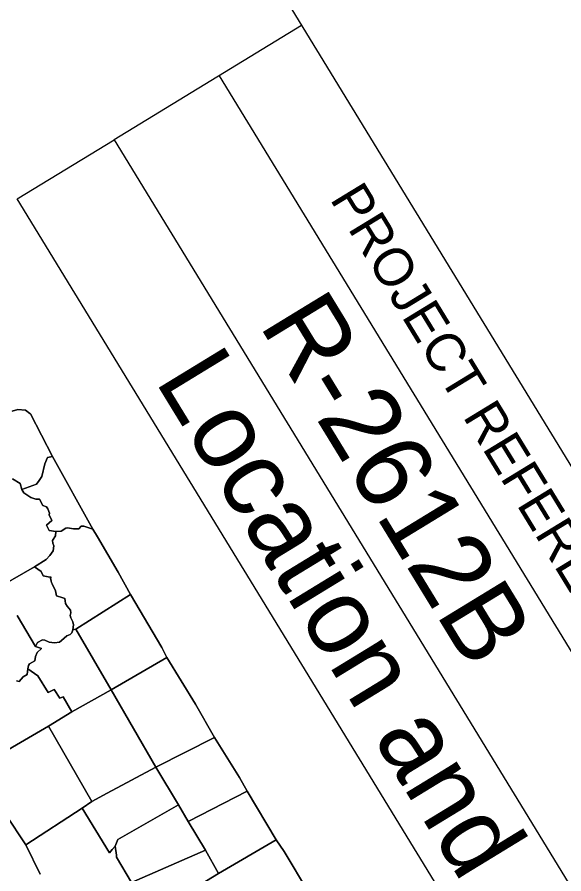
# Model space of a CAD drawing. Extents: x 1771071 to 1790027, y 804210 to 823391.
# Drawn here: x 1788245 to 1788984, y 810546 to 811705 of the extents above; entities that cross this region are included whole.
import ezdxf

# ---------------------------------------------------------------- set-up
doc = ezdxf.new("R2010")
doc.units = 0
for name, color, linetype in [('Prop Conc 2ft 6in Curb and Gutter', 7, 'Continuous'), ('Prop Horizontal Alignment', 7, 'Continuous'), ('Scratch_Level_4', 7, 'Continuous')]:
    doc.layers.add(name, color=color, linetype=linetype)

msp = doc.modelspace()

# ---------------------------------------------------------------- linework, layer by layer
at = {"layer": 'Prop Conc 2ft 6in Curb and Gutter'}
msp.add_lwpolyline([(1789711.9, 809923), (1781551.1, 823279.4), (1772201.7, 817566.9), (1780362.5, 804210.5)], close=True, dxfattribs=at)
at = {"layer": 'Prop Horizontal Alignment'}
for p, q in [((1788629.2, 811694), (1788375.8, 811539.1)), ((1788517.9, 811625.9), (1789600.1, 809854.7))]:
    msp.add_line(p, q, dxfattribs=at)
msp.add_lwpolyline([(1788375.8, 811539.1), (1789458, 809767.9), (1789327, 809687.8), (1788244.7, 811459.1)], close=True, dxfattribs=at)
at = {"layer": 'Scratch_Level_4'}
msp.add_line((1788345.5, 810643.4), (1788366.5, 810654.9), dxfattribs=at)
for points in [[(1788237.8, 811171.8), (1788245.7, 811174.1), (1788255.7, 811173.3), (1788261.7, 811168.6), (1788262.8, 811168.3), (1788292.2, 811110.3)], [(1788638.7, 810520.7), (1788605.9, 810575.8), (1788595.1, 810591.6), (1788555.6, 810657.5), (1788545.4, 810676), (1788511.8, 810730), (1788485.7, 810775.4), (1788447.3, 810838.5), (1788440.4, 810851.9), (1788398.1, 810923.7), (1788381.1, 810953.8), (1788353.3, 811001.7), (1788346.8, 811012), (1788292.2, 811110.3), (1788262.8, 811168.3), (1788261.7, 811168.6), (1788255.7, 811173.3), (1788245.7, 811174.1), (1788237.8, 811171.8)], [(1788292.2, 811110.3), (1788285.5, 811109.3), (1788282.1, 811100.6), (1788278, 811083.4), (1788274.2, 811078.2), (1788270.6, 811073.1), (1788251.1, 811065.7), (1788248.6, 811074), (1788238.1, 811080.4)], [(1788346.8, 811012), (1788334.7, 811016.3), (1788331.3, 811016), (1788328, 811012.8), (1788320.9, 811012.8), (1788312.9, 811014.1), (1788310.4, 811013.4), (1788304.2, 811009.4), (1788297, 811008.9), (1788288, 811010.2), (1788284.4, 811017.7), (1788291.4, 811023.9), (1788287.9, 811031.4), (1788288.3, 811033.7), (1788286.2, 811039.7), (1788284.3, 811042.5), (1788279.3, 811044.3), (1788275, 811052.7), (1788270, 811052.7), (1788263, 811055.2), (1788253.6, 811061.3), (1788251.1, 811065.7), (1788270.6, 811073.1), (1788274.2, 811078.2), (1788278, 811083.4), (1788282.1, 811100.6), (1788285.5, 811109.3), (1788292.2, 811110.3), (1788346.8, 811012)], [(1788238.1, 811080.4), (1788248.6, 811074), (1788251.1, 811065.7), (1788253.6, 811061.3), (1788263, 811055.2), (1788270, 811052.7), (1788275, 811052.7), (1788279.3, 811044.3), (1788284.3, 811042.5), (1788286.2, 811039.7), (1788288.3, 811033.7), (1788287.9, 811031.4), (1788291.4, 811023.9), (1788284.4, 811017.7), (1788288, 811010.2), (1788297, 811008.9)], [(1788297, 811008.9), (1788296.6, 811003), (1788292.5, 810997), (1788293, 810993.2), (1788294.2, 810989.5), (1788293.4, 810983), (1788288.7, 810976.4), (1788283.8, 810971.2), (1788268.2, 810961.1), (1788223.2, 810935.3)], [(1788324, 810877), (1788319.9, 810876), (1788321, 810882.6), (1788320, 810886.8), (1788317.1, 810892), (1788316.1, 810895.2), (1788317.4, 810899), (1788316.8, 810902.3), (1788312.3, 810908), (1788310.1, 810911.4), (1788309.7, 810915.1), (1788309, 810918.4), (1788306.2, 810919.1), (1788297.9, 810922.1), (1788296.6, 810928.7), (1788292, 810938), (1788291.1, 810940.1), (1788290.5, 810941.6), (1788289.9, 810945.7), (1788290.4, 810947), (1788286.6, 810947.6), (1788279.9, 810949.1), (1788276.9, 810954.7), (1788268.2, 810961.1), (1788283.8, 810971.2), (1788288.7, 810976.4), (1788293.4, 810983), (1788294.2, 810989.5), (1788293, 810993.2), (1788292.5, 810997), (1788296.6, 811003), (1788297, 811008.9), (1788304.2, 811009.4), (1788310.4, 811013.4), (1788312.9, 811014.1), (1788320.9, 811012.8), (1788328, 811012.8), (1788331.3, 811016), (1788334.7, 811016.3), (1788346.8, 811012), (1788353.3, 811001.7), (1788381.1, 810953.8), (1788398.1, 810923.7), (1788324, 810877)], [(1788223.2, 810935.3), (1788268.2, 810961.1), (1788276.9, 810954.7), (1788279.9, 810949.1), (1788286.6, 810947.6), (1788290.4, 810947), (1788289.9, 810945.7), (1788290.5, 810941.6), (1788291.1, 810940.1), (1788292, 810938), (1788296.6, 810928.7), (1788297.9, 810922.1), (1788306.2, 810919.1), (1788309, 810918.4), (1788309.7, 810915.1), (1788310.1, 810911.4), (1788312.3, 810908), (1788316.8, 810902.3)], [(1788447.3, 810838.5), (1788371.9, 810794.9), (1788324, 810877), (1788398.1, 810923.7), (1788440.4, 810851.9), (1788447.3, 810838.5)], [(1788316.8, 810902.3), (1788317.4, 810899), (1788316.1, 810895.2), (1788317.1, 810892), (1788320, 810886.8), (1788321, 810882.6), (1788319.9, 810876), (1788318.7, 810871.9), (1788316.2, 810869.5), (1788311.7, 810867.6), (1788304.7, 810861.6), (1788301.8, 810859), (1788295.2, 810858.1), (1788288.1, 810859.1), (1788282.2, 810862.1), (1788279, 810862.2), (1788272.3, 810858.7), (1788269.3, 810853.2), (1788244.4, 810895.5)], [(1788244.4, 810895.5), (1788269.3, 810853.2), (1788273.4, 810852), (1788277.4, 810850.8)], [(1788324, 810877), (1788371.9, 810794.9), (1788318.7, 810764.9), (1788306.8, 810785.3), (1788302.3, 810783.5), (1788294.7, 810795.1), (1788286.5, 810791), (1788272.7, 810813.6), (1788259, 810822.9), (1788259.9, 810827.6), (1788261.3, 810830), (1788268.5, 810834), (1788269.2, 810839.9), (1788271.6, 810845.2), (1788277.4, 810850.8), (1788273.4, 810852), (1788269.3, 810853.2), (1788272.3, 810858.7), (1788279, 810862.2), (1788282.2, 810862.1), (1788288.1, 810859.1), (1788295.2, 810858.1), (1788301.8, 810859), (1788304.7, 810861.6), (1788311.7, 810867.6), (1788316.2, 810869.5), (1788318.7, 810871.9), (1788319.9, 810876), (1788324, 810877)], [(1788277.4, 810850.8), (1788271.6, 810845.2), (1788269.2, 810839.9), (1788268.5, 810834), (1788261.3, 810830), (1788259.9, 810827.6), (1788259, 810822.9), (1788258.2, 810815.5), (1788252.8, 810812.2), (1788247.3, 810806.1), (1788243.5, 810806.7)], [(1788485.7, 810775.4), (1788511.8, 810730), (1788432.4, 810689.9), (1788371.9, 810794.9), (1788447.3, 810838.5), (1788485.7, 810775.4)], [(1788243.5, 810806.7), (1788247.3, 810806.1), (1788252.8, 810812.2), (1788258.2, 810815.5), (1788259, 810822.9), (1788272.7, 810813.6), (1788286.5, 810791), (1788294.7, 810795.1), (1788302.3, 810783.5), (1788306.8, 810785.3)], [(1788432.4, 810689.9), (1788366.5, 810654.9), (1788345.5, 810643.4), (1788287.2, 810745.7), (1788318.7, 810764.9), (1788371.9, 810794.9), (1788432.4, 810689.9)], [(1788371.9, 810794.9), (1788318.7, 810764.9), (1788287.2, 810745.7), (1788345.5, 810643.4)], [(1788366.5, 810654.9), (1788432.4, 810689.9), (1788371.9, 810794.9)], [(1788306.8, 810785.3), (1788318.7, 810764.9), (1788287.2, 810745.7), (1788187.1, 810687.3)], [(1788332.7, 810634.4), (1788256.5, 810585), (1788228.6, 810626.5), (1788187.1, 810687.3), (1788287.2, 810745.7), (1788345.5, 810643.4), (1788332.7, 810634.4)], [(1788555.6, 810657.5), (1788475.9, 810616.3), (1788463, 810639), (1788432.4, 810689.9), (1788511.8, 810730), (1788545.4, 810676), (1788555.6, 810657.5)], [(1788377.3, 810583.3), (1788373, 810578.4), (1788369.4, 810574.1), (1788332.7, 810634.4), (1788345.5, 810643.4), (1788366.5, 810654.9), (1788432.4, 810689.9), (1788463, 810639), (1788380.8, 810592.1), (1788377.3, 810583.3)], [(1788555.6, 810657.5), (1788595.1, 810591.6), (1788516.8, 810545.9), (1788499.4, 810577.5), (1788475.9, 810616.3), (1788555.6, 810657.5)], [(1788475.9, 810616.3), (1788499.4, 810577.5), (1788399.1, 810533.8), (1788379.2, 810568.1), (1788379.1, 810570.9), (1788377.3, 810583.3), (1788380.8, 810592.1), (1788463, 810639), (1788475.9, 810616.3)], [(1788155.7, 810543.9), (1788158.5, 810551), (1788159.1, 810557.9), (1788164.9, 810560.9), (1788170.3, 810567.3), (1788171.6, 810571), (1788169.4, 810574.7), (1788169, 810577.3), (1788171.7, 810580.2), (1788185.8, 810588.3), (1788210.7, 810611.2), (1788228.6, 810626.5), (1788256.5, 810585), (1788275.5, 810545.3)], [(1788275.5, 810545.3), (1788256.5, 810585), (1788332.7, 810634.4), (1788369.4, 810574.1), (1788373, 810578.4), (1788377.3, 810583.3), (1788379.1, 810570.9), (1788379.2, 810568.1), (1788399.1, 810533.8)], [(1788638.7, 810520.7), (1788618.9, 810522.7), (1788614.6, 810522.1), (1788540.5, 810477.4), (1788531.2, 810471.6), (1788525.7, 810470.6), (1788507.7, 810467.2), (1788505.1, 810462.3), (1788495.9, 810459.1), (1788490.8, 810497.2), (1788481.7, 810511.4), (1788478, 810509.2), (1788478, 810516.3), (1788480.1, 810522.5), (1788486.9, 810527.6), (1788516.8, 810545.9), (1788595.1, 810591.6), (1788605.9, 810575.8), (1788638.7, 810520.7)], [(1788499.4, 810577.5), (1788516.8, 810545.9), (1788486.9, 810527.6), (1788480.1, 810522.5), (1788478, 810516.3), (1788478, 810509.2), (1788473.3, 810506), (1788473.6, 810502.6), (1788476.9, 810499.6), (1788476.6, 810495.9), (1788471.1, 810492), (1788464.6, 810489.2), (1788453.5, 810488.8), (1788444.4, 810491.6), (1788440.7, 810500.1), (1788420.1, 810497.4), (1788412.5, 810508.6), (1788399.1, 810533.8), (1788499.4, 810577.5)]]:
    msp.add_lwpolyline(points, dxfattribs=at)

# ---------------------------------------------------------------- texts
at = {"layer": 'Prop Horizontal Alignment'}
for s, height, p in [('PROJECT REFERENCE NO.', 52.175, (1788666.9, 811459.1)), ('R-2612B', 104.35, (1788571.1, 811288.9)), ('Location and Surveys', 104.35, (1788430.2, 811213.4))]:
    msp.add_text(s, height=height, rotation=301.4249, dxfattribs=at).set_placement(p)

doc.saveas('drawing.dxf')
